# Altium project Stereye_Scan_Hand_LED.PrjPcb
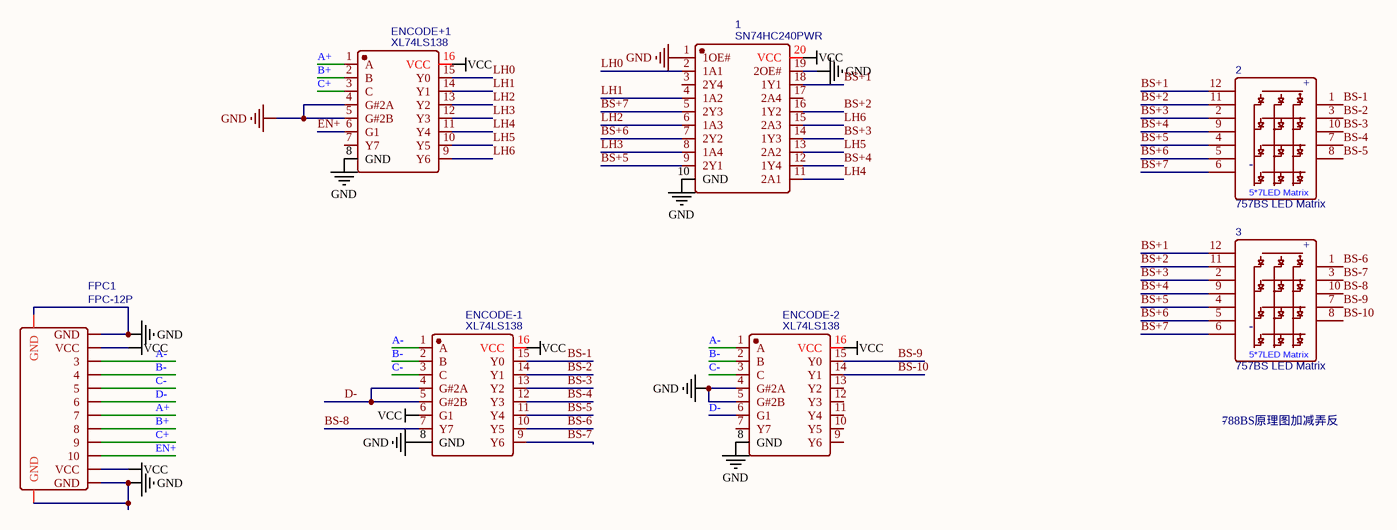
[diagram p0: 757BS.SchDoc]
1 sheet, 7 parts. Net scope: global (net labels, ports and power ports of the same name join across sheets).
Board file: 757BS.PcbDoc

## Sheet 757BS.SchDoc
size A4

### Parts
1  SN74HC240PWR  [TSSOP-20]
2  757BS LED Matrix  [757BS]
3  757BS LED Matrix  [757BS]
ENCODE+1  XL74LS138  [SOP-16]
ENCODE-1  XL74LS138  [SOP-16]
ENCODE-2  XL74LS138  [SOP-16]
FPC1  FPC-12P  [FPC-0.5MM-12P]

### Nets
GND: 1.1(1OE#) 1.10(GND) 1.19(2OE#) ENCODE+1.4(G#2A) ENCODE+1.5(G#2B) ENCODE+1.8(GND) ENCODE-1.8(GND) ENCODE-2.4(G#2A) ENCODE-2.5(G#2B) ENCODE-2.8(GND) FPC1.1(GND) FPC1.12(GND) FPC1.13(GND) FPC1.14(GND)
VCC: 1.20(VCC) ENCODE+1.16(VCC) ENCODE-1.6(G1) ENCODE-1.16(VCC) ENCODE-2.16(VCC) FPC1.2(VCC) FPC1.11(VCC)
A+: ENCODE+1.1(A) FPC1.7
A-: ENCODE-1.1(A) ENCODE-2.1(A) FPC1.3
B+: ENCODE+1.2(B) FPC1.8
B-: ENCODE-1.2(B) ENCODE-2.2(B) FPC1.4
BS+1: 1.18(1Y1) 2.12 3.12
BS+2: 1.16(1Y2) 2.11 3.11
BS+3: 1.14(1Y3) 2.2 3.2
BS+4: 1.12(1Y4) 2.9 3.9
BS+5: 1.9(2Y1) 2.4 3.4
BS+6: 1.7(2Y2) 2.5 3.5
BS+7: 1.5(2Y3) 2.6 3.6
BS-1: 2.1 ENCODE-1.15(Y0)
BS-2: 2.3 ENCODE-1.14(Y1)
BS-3: 2.10 ENCODE-1.13(Y2)
BS-4: 2.7 ENCODE-1.12(Y3)
BS-5: 2.8 ENCODE-1.11(Y4)
BS-6: 3.1 ENCODE-1.10(Y5)
BS-7: 3.3 ENCODE-1.9(Y6)
BS-8: 3.10 ENCODE-1.7(Y7)
BS-9: 3.7 ENCODE-2.15(Y0)
BS-10: 3.8 ENCODE-2.14(Y1)
C+: ENCODE+1.3(C) FPC1.9
C-: ENCODE-1.3(C) ENCODE-2.3(C) FPC1.5
D-: ENCODE-1.4(G#2A) ENCODE-1.5(G#2B) ENCODE-2.6(G1) FPC1.6
EN+: ENCODE+1.6(G1) FPC1.10
LH0: 1.2(1A1) ENCODE+1.15(Y0)
LH1: 1.4(1A2) ENCODE+1.14(Y1)
LH2: 1.6(1A3) ENCODE+1.13(Y2)
LH3: 1.8(1A4) ENCODE+1.12(Y3)
LH4: 1.11(2A1) ENCODE+1.11(Y4)
LH5: 1.13(2A2) ENCODE+1.10(Y5)
LH6: 1.15(2A3) ENCODE+1.9(Y6)

Not connected (* = marked no-connect by the designer): 1 3(2Y4) 17(2A4); ENCODE+1 7(Y7); ENCODE-2 7(Y7) 9(Y6) 10(Y5) 11(Y4) 12(Y3) 13(Y2)

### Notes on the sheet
- -
- 788BS原理图加减弄反

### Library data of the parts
1 = SN74HC240PWR: BOM_Manufacturer: Texas Instruments; Contributor: LCSC
2 3 = 757BS: Contributor: fzx399
ENCODE+1 ENCODE-1 ENCODE-2 = XL74LS138: BOM_Manufacturer: XINLUDA; Contributor: LCSC
FPC1 = FPC-12P: BOM_Manufacturer: JUSHUO; BOM_Manufacturer Part: AFC01-S12FCA-00; Contributor: zhqtl2002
